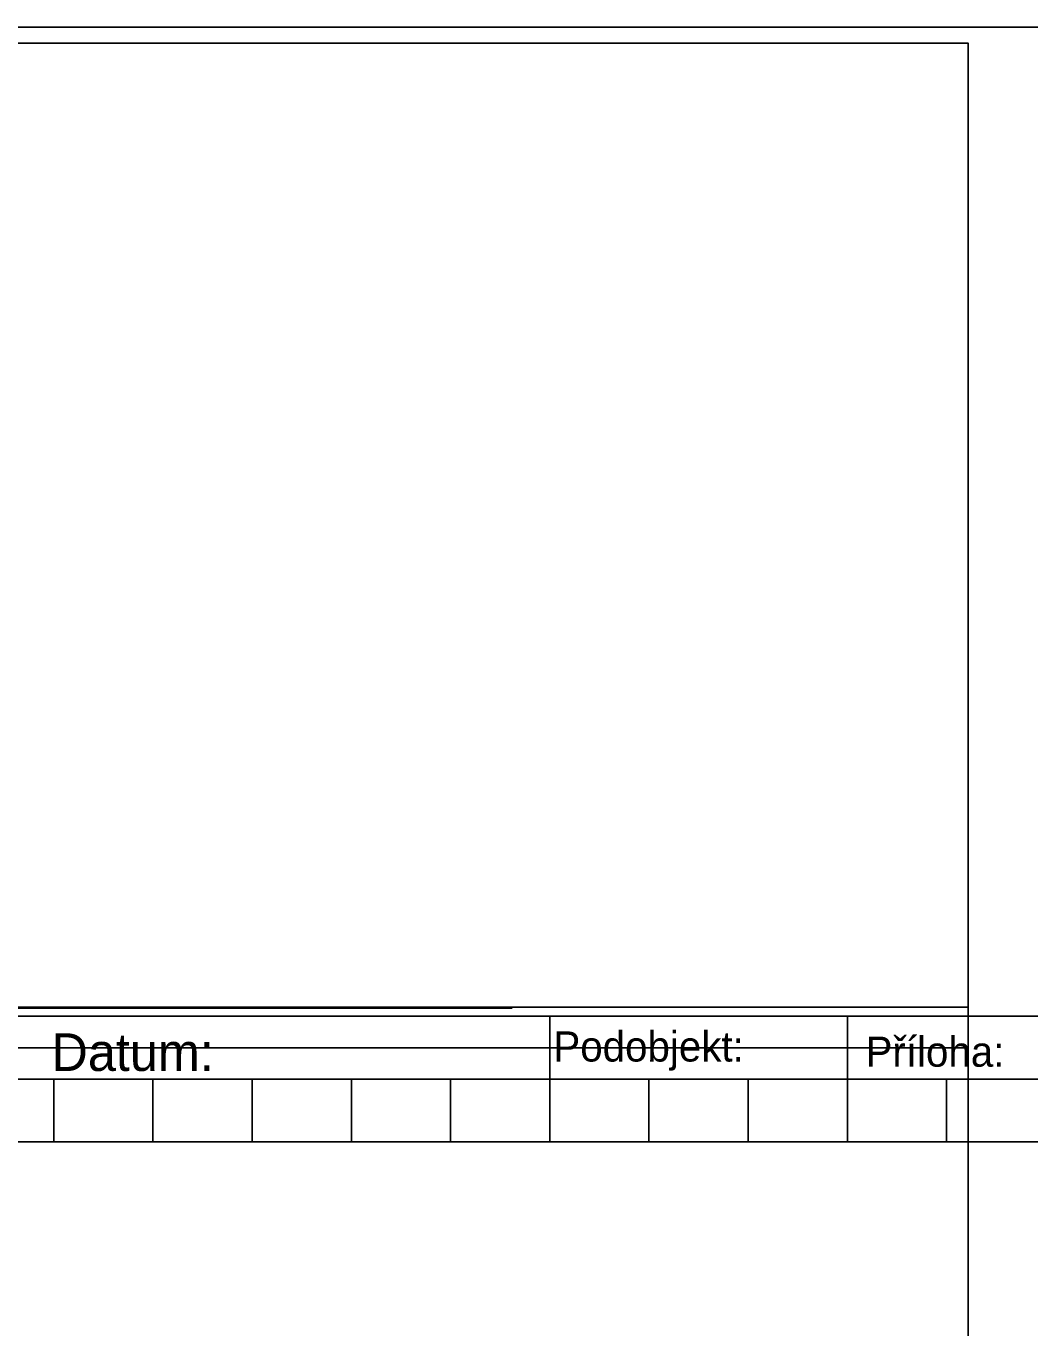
# Model space of a CAD drawing. Extents: x 1391 to 5528, y -6194 to 565.
# Drawn here: x 4157 to 4557, y -3090 to -2572 of the extents above; entities that cross this region are included whole.
import ezdxf

# ---------------------------------------------------------------- set-up
doc = ezdxf.new("R2010")
doc.units = 0
for name, color, linetype in [('Vrstva 11', 7, 'Continuous'), ('Vrstva 2', 7, 'Continuous'), ('Vrstva 3', 7, 'Continuous'), ('Vrstva 8', 7, 'Continuous')]:
    doc.layers.add(name, color=color, linetype=linetype)

# ---------------------------------------------------------------- blocks, each defined once
blk = doc.blocks.new('_U1')
at = {"layer": 'Vrstva 8'}
for p, q in [((3.35, 0.25), (3.35, -0.25)), ((4.535, 0.25), (4.535, -0.25)), ((8.5, 0), (-8.5, 0)), ((1.375, 0), (1.375, -0.25)), ((1.77, 0), (1.77, -0.25)), ((2.165, 0), (2.165, -0.25)), ((2.56, 0), (2.56, -0.25)), ((2.955, 0), (2.955, -0.25)), ((3.745, 0), (3.745, -0.25)), ((4.14, 0), (4.14, -0.25)), ((4.93, 0), (4.93, -0.25))]:
    blk.add_line(p, q, dxfattribs=at)
blk.add_lwpolyline([(-8.5, 0.25), (8.5, 0.25), (8.5, -0.25), (-8.5, -0.25)], close=True, dxfattribs=at)
for s, p in [('Podobjekt:', (3.3643, 0.0699)), ('Příloha:', (4.6073, 0.0493))]:
    blk.add_text(s, height=0.12, dxfattribs=at).set_placement(p)
blk = doc.blocks.new('_U2')
at = {"layer": 'Vrstva 3'}
blk.add_line((-2.6675, -1.82505), (2.6675, -1.82505), dxfattribs=at)
for s, p in [('Razítko oprávněné osoby:', (-2.5675, 1.92495)), ('Podpis:', (-2.5675, -2.07505)), ('Datum:', (0.8325, -2.07505))]:
    blk.add_text(s, height=0.15, dxfattribs=at).set_placement(p)
blk = doc.blocks.new('_U3')
at = {"layer": 'Vrstva 2'}
blk.add_lwpolyline([(-5.33255, 2.00005), (5.33245, 2.00005), (5.33245, -1.99995), (-5.33255, -1.99995)], close=True, dxfattribs=at)

msp = doc.modelspace()

# ---------------------------------------------------------------- linework, layer by layer
at = {"layer": 'Vrstva 11'}
msp.add_line((1390.73, -2572.48), (5438.99, -2572.48), dxfattribs=at)

# ---------------------------------------------------------------- block references
at = {"layer": 'Vrstva 2', "xscale": 100, "yscale": 100}
for p in [(3998.89, -2778.77), (3998.89, -3162.62)]:
    msp.add_blockref('_U3', p, dxfattribs=at)
at = {"layer": 'Vrstva 3', "xscale": 100, "yscale": 100}
for p in [(4083.89, -2780.51), (4083.89, -3164.37)]:
    msp.add_blockref('_U2', p, dxfattribs=at)
at = {"layer": 'Vrstva 8', "xscale": 100, "yscale": 100}
msp.add_blockref('_U1', (4030.56, -2991.26), dxfattribs=at)

doc.saveas('drawing.dxf')
